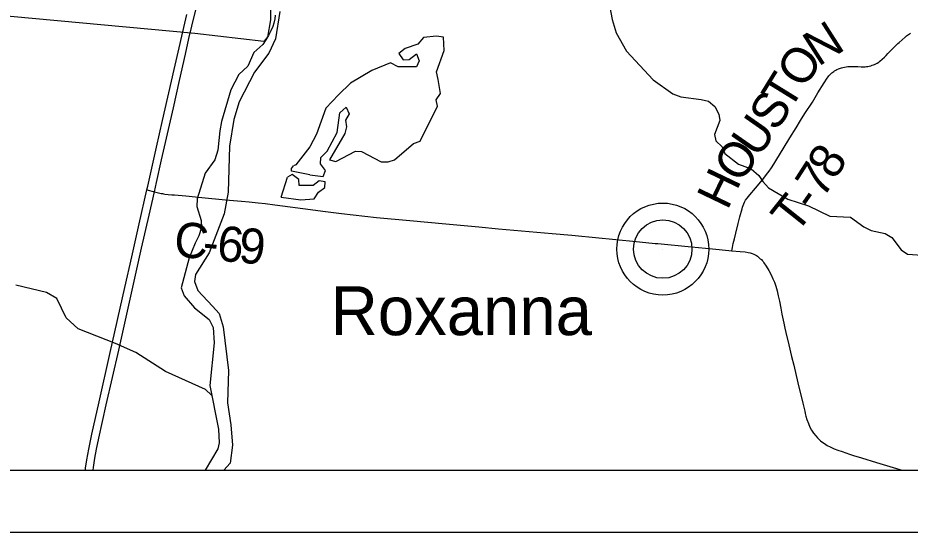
# Model space of a CAD drawing. Extents: x -19.5 to 44.1, y 0 to 22.
# Drawn here: x -17.865 to -16.421, y 14 to 14.832 of the extents above; entities that cross this region are included whole.
import ezdxf

# ---------------------------------------------------------------- set-up
doc = ezdxf.new("R2010")
doc.units = 0
for name, color, linetype in [('GM_X_County_Road', 7, 'Continuous'), ('GM_X_County_Road_Text', 7, 'Continuous'), ('GM_X_Major_River', 7, 'Continuous'), ('GM_X_Minor_Lake', 7, 'Continuous'), ('GM_X_Minor_River', 7, 'Continuous'), ('GM_X_Section', 7, 'Continuous'), ('GM_X_Township_Road', 7, 'Continuous'), ('GM_X_Township_Road_Text', 7, 'Continuous'), ('GM_X_Unincorporated', 7, 'Continuous'), ('GM_X_Unincorporated_Location', 7, 'Continuous'), ('GM_X_Unincorporated_Text', 7, 'Continuous'), ('GM_X_US_Route', 7, 'Continuous'), ('SH_Data', 7, 'Continuous')]:
    doc.layers.add(name, color=color, linetype=linetype)

msp = doc.modelspace()

# ---------------------------------------------------------------- linework, layer by layer
at = {"layer": 'GM_X_County_Road'}
for points in [[(-17.6559, 14.5534), (-17.6438, 14.5504)], [(-17.6438, 14.5504), (-17.635, 14.5483), (-17.6329, 14.5478), (-17.631, 14.5475), (-17.6292, 14.5471), (-17.6272, 14.5469), (-17.6214, 14.5462), (-17.6158, 14.5457), (-17.6111, 14.5453), (-17.5931, 14.5439), (-17.5672, 14.5414), (-17.5286, 14.5375), (-17.503, 14.5353), (-17.4905, 14.5342), (-17.4758, 14.5326), (-17.4648, 14.5313), (-17.4489, 14.5292)], [(-17.4489, 14.5292), (-17.3912, 14.5219), (-17.3715, 14.519), (-17.341, 14.5151), (-17.2846, 14.5088), (-17.2305, 14.504), (-17.1724, 14.4986), (-17.1186, 14.4938), (-17.0872, 14.4908), (-16.9999, 14.483), (-16.9684, 14.4801), (-16.9245, 14.4759), (-16.9023, 14.4738), (-16.8587, 14.4697), (-16.8333, 14.4671)], [(-16.8333, 14.4671), (-16.8292, 14.4667), (-16.7746, 14.4616), (-16.7404, 14.4582), (-16.7144, 14.4556), (-16.7094, 14.4551)], [(-16.7094, 14.4551), (-16.6958, 14.454), (-16.6878, 14.4531), (-16.6829, 14.4524), (-16.6798, 14.4516), (-16.6765, 14.4506), (-16.6736, 14.4495), (-16.6714, 14.4483), (-16.6694, 14.4472), (-16.6679, 14.4463), (-16.6659, 14.4449), (-16.6632, 14.4423), (-16.6615, 14.4407), (-16.6601, 14.4391), (-16.6588, 14.4375), (-16.6574, 14.4357), (-16.6537, 14.43), (-16.6496, 14.4231), (-16.6458, 14.4159), (-16.6428, 14.4098), (-16.6403, 14.4041), (-16.638, 14.3976), (-16.6361, 14.3904), (-16.6341, 14.382), (-16.6322, 14.3735), (-16.6301, 14.3625), (-16.6283, 14.3527), (-16.6253, 14.3382), (-16.6234, 14.3299), (-16.6217, 14.3228), (-16.6169, 14.3029), (-16.6125, 14.2843), (-16.6091, 14.27), (-16.6024, 14.2417), (-16.5945, 14.2084), (-16.5914, 14.1958)], [(-16.5914, 14.1958), (-16.5905, 14.1919), (-16.5894, 14.1877), (-16.5878, 14.1824), (-16.5853, 14.1755), (-16.5829, 14.1698), (-16.5803, 14.165), (-16.577, 14.1599), (-16.5735, 14.1556), (-16.5705, 14.1525), (-16.5657, 14.1478), (-16.5634, 14.146), (-16.5593, 14.1432), (-16.555, 14.1404), (-16.5504, 14.1381), (-16.5436, 14.135), (-16.5378, 14.1327), (-16.531, 14.1303), (-16.5188, 14.1263), (-16.5122, 14.1241), (-16.4994, 14.12), (-16.475, 14.1128), (-16.4376, 14.1013), (-16.4337, 14.1)]]:
    msp.add_lwpolyline(points, dxfattribs=at)
at = {"layer": 'GM_X_Major_River'}
for points in [[(-17.4559, 14.8532), (-17.456, 14.8284), (-17.4606, 14.8008), (-17.4686, 14.7889), (-17.4831, 14.7757), (-17.4926, 14.7536), (-17.5074, 14.74), (-17.5204, 14.7153), (-17.5353, 14.664), (-17.5381, 14.6493), (-17.541, 14.6178), (-17.546, 14.602), (-17.5619, 14.5805), (-17.5747, 14.539), (-17.5754, 14.5269), (-17.5682, 14.5038), (-17.5674, 14.4928), (-17.572, 14.4792), (-17.5777, 14.4676), (-17.5876, 14.4436), (-17.6005, 14.395), (-17.5956, 14.3823), (-17.5788, 14.3627), (-17.5551, 14.3437), (-17.549, 14.331), (-17.5472, 14.3062), (-17.5543, 14.2372), (-17.5402, 14.1668), (-17.539, 14.1447), (-17.5413, 14.1345), (-17.5617, 14.1)], [(-17.4411, 14.842), (-17.4478, 14.7978), (-17.4584, 14.7749), (-17.4819, 14.7437), (-17.5066, 14.6958), (-17.5154, 14.6676), (-17.5225, 14.6241), (-17.5245, 14.5496), (-17.531, 14.5148), (-17.555, 14.4517), (-17.5771, 14.4167), (-17.5789, 14.4053), (-17.5733, 14.3907), (-17.5498, 14.3656), (-17.5388, 14.3535), (-17.5323, 14.332), (-17.5239, 14.2617), (-17.5256, 14.2089), (-17.5202, 14.1734), (-17.5175, 14.1406), (-17.5215, 14.1118), (-17.5315, 14.1)]]:
    msp.add_lwpolyline(points, dxfattribs=at)
at = {"layer": 'GM_X_Minor_Lake'}
for points in [[(-17.3923, 14.578), (-17.3707, 14.5753), (-17.3671, 14.5851), (-17.3752, 14.5955), (-17.3743, 14.6058), (-17.3642, 14.6162), (-17.348, 14.6466), (-17.3436, 14.6784), (-17.3336, 14.6873), (-17.3285, 14.6766), (-17.3344, 14.6665), (-17.3331, 14.6554), (-17.3359, 14.6448), (-17.3603, 14.6024), (-17.3501, 14.5992), (-17.3183, 14.616), (-17.3088, 14.6154), (-17.2769, 14.5991), (-17.2655, 14.5989), (-17.2552, 14.6024), (-17.2247, 14.6288), (-17.2136, 14.6323), (-17.1855, 14.6891), (-17.188, 14.699), (-17.1806, 14.7095), (-17.1847, 14.732), (-17.1871, 14.7446), (-17.1751, 14.7789), (-17.1758, 14.8006), (-17.1871, 14.8024), (-17.2084, 14.7998), (-17.2174, 14.789), (-17.238, 14.7822), (-17.2484, 14.7741), (-17.2414, 14.764), (-17.2315, 14.7646), (-17.2196, 14.7734), (-17.2152, 14.7623), (-17.2196, 14.7525), (-17.2496, 14.7524), (-17.2616, 14.7588), (-17.2918, 14.7469), (-17.3264, 14.7259), (-17.3457, 14.7074), (-17.3662, 14.6858), (-17.3815, 14.6435), (-17.3921, 14.6232), (-17.4151, 14.5941), (-17.4189, 14.5926)], [(-17.3923, 14.578), (-17.4219, 14.5837), (-17.4219, 14.5884), (-17.4189, 14.5926)], [(-17.4389, 14.5418), (-17.4067, 14.5373), (-17.3854, 14.5391), (-17.3784, 14.5496), (-17.368, 14.5574), (-17.3674, 14.5668), (-17.3773, 14.5682), (-17.3869, 14.5604), (-17.4093, 14.5605), (-17.4102, 14.5704), (-17.4211, 14.5783), (-17.4284, 14.5742)], [(-17.4389, 14.5418), (-17.4284, 14.5742)]]:
    msp.add_lwpolyline(points, dxfattribs=at)
at = {"layer": 'GM_X_Minor_River'}
for points in [[(-16.9114, 14.8747), (-16.9031, 14.8294), (-16.8967, 14.8076), (-16.8799, 14.7779), (-16.8364, 14.7318), (-16.8046, 14.7087), (-16.7921, 14.7042), (-16.7588, 14.6997), (-16.7471, 14.6972), (-16.737, 14.6886), (-16.7301, 14.6759), (-16.7287, 14.666), (-16.7371, 14.6434), (-16.7354, 14.6331), (-16.725, 14.6234), (-16.7207, 14.6123), (-16.6986, 14.5951), (-16.6779, 14.5874), (-16.6656, 14.5769), (-16.6589, 14.5669), (-16.65, 14.5568), (-16.6185, 14.5386), (-16.5853, 14.5277), (-16.5507, 14.5113), (-16.517, 14.5095), (-16.4957, 14.4938), (-16.4837, 14.4879), (-16.461, 14.4828), (-16.4505, 14.4765), (-16.4353, 14.4564), (-16.4248, 14.4494), (-16.4013, 14.4481)], [(-17.5512, 14.2217), (-17.5611, 14.2309), (-17.6261, 14.26), (-17.6741, 14.2903), (-17.7069, 14.3051), (-17.7671, 14.3288), (-17.7869, 14.3467), (-17.8018, 14.3778), (-17.8187, 14.3876), (-17.8682, 14.3993)]]:
    msp.add_lwpolyline(points, dxfattribs=at)
at = {"layer": 'GM_X_Section'}
msp.add_lwpolyline([(-17.4483, 14.8362), (-17.4492, 14.8301), (-17.4508, 14.8234), (-17.4524, 14.8177), (-17.4552, 14.8109), (-17.4591, 14.8034), (-17.4634, 14.7975), (-17.4666, 14.7936), (-17.5783, 14.8063), (-17.9125, 14.8374)], dxfattribs=at)
at = {"layer": 'GM_X_Township_Road'}
msp.add_lwpolyline([(-16.7094, 14.4551), (-16.7082, 14.4605), (-16.7069, 14.4667), (-16.7052, 14.4742), (-16.7028, 14.4835), (-16.699, 14.4994), (-16.6961, 14.5102), (-16.6928, 14.5229), (-16.692, 14.5256), (-16.6911, 14.5283), (-16.6899, 14.5311), (-16.6887, 14.5337), (-16.6871, 14.5367), (-16.6846, 14.5403), (-16.6825, 14.543), (-16.6802, 14.5457), (-16.6708, 14.5564), (-16.6624, 14.5664), (-16.6577, 14.5723), (-16.653, 14.5783), (-16.649, 14.5836), (-16.6451, 14.5892), (-16.6416, 14.595), (-16.6366, 14.6031), (-16.6264, 14.6197), (-16.6153, 14.6375), (-16.6054, 14.6537), (-16.5981, 14.6656), (-16.5909, 14.677), (-16.579, 14.6955), (-16.5701, 14.7103), (-16.5598, 14.7269), (-16.5552, 14.7341), (-16.5536, 14.7363), (-16.5523, 14.738), (-16.5509, 14.7397), (-16.5492, 14.7412), (-16.5475, 14.7428), (-16.546, 14.744), (-16.5445, 14.745), (-16.543, 14.7459), (-16.5412, 14.747), (-16.5393, 14.748), (-16.5368, 14.7491), (-16.5349, 14.7498), (-16.532, 14.7509), (-16.5296, 14.7516), (-16.5268, 14.7522), (-16.5243, 14.7526), (-16.5214, 14.7529), (-16.5193, 14.753), (-16.5166, 14.7531), (-16.5134, 14.7531), (-16.5052, 14.7529), (-16.4998, 14.7527), (-16.4961, 14.7526), (-16.4935, 14.7527), (-16.4913, 14.753), (-16.4891, 14.7533), (-16.4868, 14.7537), (-16.4844, 14.7544), (-16.4821, 14.7551), (-16.4802, 14.7557), (-16.4785, 14.7564), (-16.4762, 14.7575), (-16.474, 14.7586), (-16.4716, 14.7602), (-16.4697, 14.7616), (-16.4661, 14.7648), (-16.4624, 14.7684), (-16.4598, 14.7711), (-16.4569, 14.7743), (-16.4515, 14.7796), (-16.4461, 14.7848), (-16.4408, 14.7901), (-16.4384, 14.7922), (-16.4288, 14.8005), (-16.4264, 14.8025), (-16.425, 14.8036), (-16.4232, 14.8049), (-16.4216, 14.8061), (-16.4199, 14.8071)], dxfattribs=at)
at = {"layer": 'GM_X_Unincorporated'}
for radius in [0.0744, 0.0472]:
    msp.add_circle((-16.821, 14.4578), radius, dxfattribs=at)
at = {"layer": 'GM_X_Unincorporated_Location'}
msp.add_line((-16.821, 14.4578), (-16.821, 14.4578), dxfattribs=at)
at = {"layer": 'GM_X_US_Route'}
for points in [[(-17.7428, 14.1), (-17.7423, 14.1046), (-17.7401, 14.1194), (-17.7375, 14.1341), (-17.7339, 14.1518), (-17.7218, 14.2057), (-17.7016, 14.2942), (-17.6645, 14.4591), (-17.6525, 14.5124), (-17.6438, 14.5504), (-17.6403, 14.5657), (-17.6324, 14.6021), (-17.6244, 14.6373), (-17.6132, 14.6863), (-17.6033, 14.7306), (-17.5936, 14.773), (-17.5879, 14.7985), (-17.5832, 14.8184), (-17.5754, 14.8511)], [(-17.7556, 14.1), (-17.7552, 14.1036), (-17.7531, 14.1171), (-17.75, 14.1342), (-17.7451, 14.1586), (-17.7335, 14.2107), (-17.7154, 14.2907), (-17.6916, 14.3956), (-17.6804, 14.4453), (-17.6684, 14.4986), (-17.6559, 14.5534), (-17.6544, 14.5598), (-17.6404, 14.6229), (-17.6306, 14.6659), (-17.612, 14.7484), (-17.5914, 14.8374)]]:
    msp.add_lwpolyline(points, dxfattribs=at)
at = {"layer": 'SH_Data'}
for p, q in [((-19.213, 14.1), (-12.413, 14.1)), ((-19.313, 14), (-12.313, 14))]:
    msp.add_line(p, q, dxfattribs=at)

# ---------------------------------------------------------------- texts
at = {"layer": 'GM_X_County_Road_Text'}
for s, rotation, p in [('C', 354.5294, (-17.6138, 14.4462)), ('6', 354.6199, (-17.544, 14.4395)), ('9', 354.9204, (-17.5088, 14.4362)), ('-', 354.5508, (-17.5673, 14.4417))]:
    msp.add_text(s, height=0.0568, rotation=rotation, dxfattribs=at).set_placement(p)
at = {"layer": 'GM_X_Township_Road_Text'}
for s, rotation, p in [('N', 32.5695, (-16.5696, 14.7521)), ('O', 55.2485, (-16.5938, 14.7151)), ('T', 58.3287, (-16.6157, 14.6796)), ('S', 57.2024, (-16.6371, 14.6463)), ('U', 55.0927, (-16.667, 14.6034)), ('O', 54.7003, (-16.6961, 14.5623)), ('8', 57.9515, (-16.5427, 14.5679)), ('7', 57.3274, (-16.562, 14.5378)), ('H', 64.3538, (-16.7165, 14.5194)), ('T', 51.5172, (-16.6055, 14.4804)), ('-', 54.8959, (-16.5769, 14.5166))]:
    msp.add_text(s, height=0.0568, rotation=rotation, dxfattribs=at).set_placement(p)
at = {"layer": 'GM_X_Unincorporated_Text'}
msp.add_text('Roxanna', height=0.07898, rotation=0, dxfattribs=at).set_placement((-17.3585, 14.3186))

doc.saveas('drawing.dxf')
